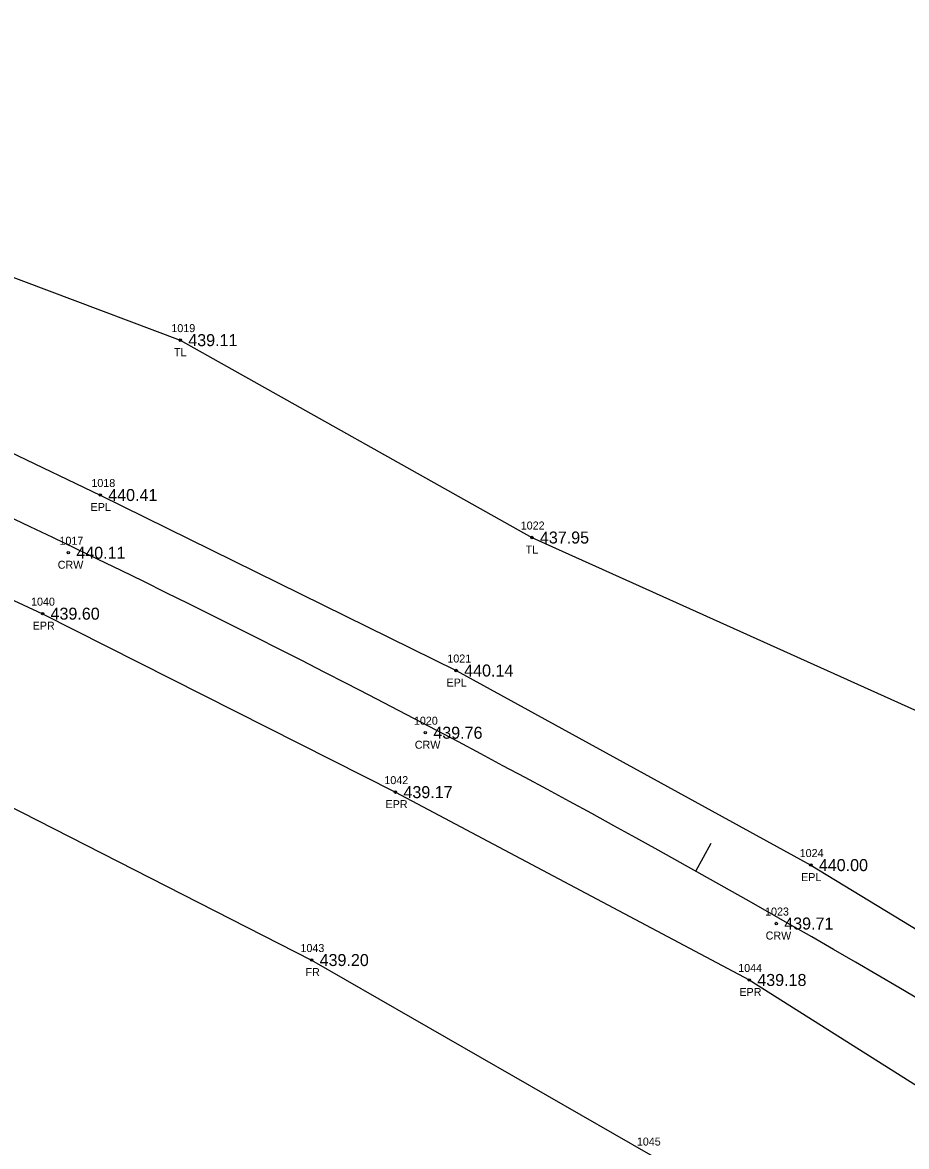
# Model space of a CAD drawing. Extents: x 1611865 to 1617004, y 775289 to 778546.
# Drawn here: x 1613950.5 to 1614060.8, y 777980.8 to 778121.2 of the extents above; entities that cross this region are included whole.
import ezdxf

# ---------------------------------------------------------------- set-up
doc = ezdxf.new("R2010")
doc.units = 0
for name, color, linetype in [('Default', 7, 'Continuous'), ('RD_EX_Fence_Other', 7, 'Continuous'), ('RD_EX_Fence_Other_txCode', 7, 'Continuous'), ('RD_EX_Road', 7, 'Continuous'), ('RD_EX_Road_txCode', 7, 'Continuous'), ('RD_EX_TX_Fence_Other_ELEV', 7, 'Continuous'), ('RD_EX_TX_Road_ELEV', 7, 'Continuous'), ('RD_EX_TX_VEG_ELEV', 7, 'Continuous'), ('RD_EX_VEG', 7, 'Continuous'), ('RD_EX_VEG_txCode', 7, 'Continuous'), ('RD_HC_Cl', 7, 'Continuous'), ('RD_HC_Data_Tic', 7, 'Continuous'), ('RD_HC_Survey_ELEV', 7, 'Continuous'), ('RD_HC_Survey_txCode', 7, 'Continuous'), ('RD_SMD_Locator', 7, 'Continuous')]:
    doc.layers.add(name, color=color, linetype=linetype)

msp = doc.modelspace()

# ---------------------------------------------------------------- linework, layer by layer
at = {"layer": 'Default'}
msp.add_arc((1613334.62, 776765.46), 1432.38, 51.01411, 67.14296, dxfattribs=at)
msp.add_arc((1613334.62, 776765.46), 1432.38, 51.01411, 67.14296, dxfattribs=at)
at = {"layer": 'RD_EX_Fence_Other'}
msp.add_lwpolyline([(1613852.08, 778066.01), (1613898.03, 778046.63), (1613942.24, 778026.73), (1613986.54, 778004.12), (1614028.52, 777979.95), (1614066.85, 777959.39), (1614112.82, 777929.4), (1614150.64, 777902.78), (1614189.71, 777873.35), (1614229.91, 777841.27), (1614268.42, 777810.69), (1614347.33, 777746.8), (1614401.12, 777703.98), (1614396.2, 777691.06)], dxfattribs=at)
at = {"layer": 'RD_EX_Road'}
for points in [[(1613868.87, 778104.15), (1613915.02, 778083.82), (1613960.16, 778062.2), (1614004.58, 778040.28), (1614048.84, 778015.98), (1614091.38, 777990.08), (1614134.36, 777962.6), (1614174.73, 777933.48), (1614192.07, 777920.58), (1614215.93, 777904.23), (1614254.59, 777873.05), (1614293.82, 777842.42), (1614371.74, 777779.59), (1614449.33, 777716.3), (1614443.98, 777709.72), (1614439.38, 777704.09)], [(1613862.14, 778087.92), (1613908.12, 778068.22), (1613952.96, 778047.38), (1613997, 778025.09), (1614041.16, 778001.63), (1614124.35, 777949.06), (1614164.51, 777920.91), (1614187.11, 777904.29), (1614205.27, 777889.82), (1614244.49, 777859.52), (1614283.42, 777829.45), (1614361.06, 777765.89), (1614439.38, 777704.09)]]:
    msp.add_lwpolyline(points, dxfattribs=at)
at = {"layer": 'RD_EX_VEG'}
msp.add_lwpolyline([(1613877.31, 778121.22), (1613921.05, 778100.02), (1613970.15, 778081.54), (1614014.03, 778056.89), (1614062.61, 778034.99), (1614105.06, 778008.15), (1614147.57, 777982.51), (1614187.98, 777952.84), (1614226.4, 777922.61), (1614267.62, 777889.85), (1614307.16, 777859.76), (1614385.12, 777793.65), (1614491.14, 777728.5)], dxfattribs=at)
at = {"layer": 'RD_HC_Cl'}
msp.add_arc((1613334.62, 776765.46), 1432.38, 51.01411, 67.14296, dxfattribs=at)
at = {"layer": 'RD_HC_Data_Tic'}
msp.add_line((1614034.47, 778015.22), (1614036.42, 778018.71), dxfattribs=at)
at = {"layer": 'RD_SMD_Locator'}
for centre in [(1613970.15, 778081.54), (1613960.16, 778062.2), (1614014.03, 778056.89), (1613956.18, 778054.99), (1613952.96, 778047.38), (1614004.58, 778040.28), (1614000.73, 778032.51), (1613997, 778025.09), (1614048.84, 778015.98), (1614044.52, 778008.68), (1613986.54, 778004.12), (1614041.16, 778001.63)]:
    msp.add_circle(centre, 0.15, dxfattribs=at)

# ---------------------------------------------------------------- texts
at = {"layer": 'RD_EX_Fence_Other_txCode'}
for s, p in [('1043', (1613985.15, 778005.12)), ('FR', (1613985.78, 778002.12)), ('1045', (1614027.13, 777980.95))]:
    msp.add_text(s, height=1, dxfattribs=at).set_placement(p)
at = {"layer": 'RD_EX_Road_txCode'}
for s, p in [('1018', (1613959.06, 778063.2)), ('EPL', (1613958.96, 778060.2)), ('1040', (1613951.53, 778048.38)), ('EPR', (1613951.73, 778045.38)), ('1021', (1614003.48, 778041.28)), ('EPL', (1614003.38, 778038.28)), ('1042', (1613995.62, 778026.09)), ('EPR', (1613995.77, 778023.09)), ('1024', (1614047.45, 778016.98)), ('EPL', (1614047.63, 778013.98)), ('1044', (1614039.78, 778002.63)), ('EPR', (1614039.93, 777999.63))]:
    msp.add_text(s, height=1, dxfattribs=at).set_placement(p)
at = {"layer": 'RD_EX_TX_Fence_Other_ELEV'}
msp.add_text('439.20', height=1.5, dxfattribs=at).set_placement((1613987.54, 778003.37))
at = {"layer": 'RD_EX_TX_Road_ELEV'}
for s, p in [('440.41', (1613961.16, 778061.45)), ('439.60', (1613953.96, 778046.63)), ('440.14', (1614005.58, 778039.53)), ('439.17', (1613998, 778024.34)), ('440.00', (1614049.84, 778015.23)), ('439.18', (1614042.16, 778000.88))]:
    msp.add_text(s, height=1.5, dxfattribs=at).set_placement(p)
at = {"layer": 'RD_EX_TX_VEG_ELEV'}
for s, p in [('439.11', (1613971.15, 778080.79)), ('437.95', (1614015.03, 778056.14))]:
    msp.add_text(s, height=1.5, dxfattribs=at).set_placement(p)
at = {"layer": 'RD_EX_VEG_txCode'}
for s, p in [('1019', (1613969.04, 778082.54)), ('TL', (1613969.37, 778079.54)), ('1022', (1614012.64, 778057.89)), ('TL', (1614013.26, 778054.89))]:
    msp.add_text(s, height=1, dxfattribs=at).set_placement(p)
at = {"layer": 'RD_HC_Survey_ELEV'}
for s, p in [('440.11', (1613957.18, 778054.24)), ('439.76', (1614001.73, 778031.76)), ('439.71', (1614045.52, 778007.93))]:
    msp.add_text(s, height=1.5, dxfattribs=at).set_placement(p)
at = {"layer": 'RD_HC_Survey_txCode'}
for s, p in [('1017', (1613955.08, 778055.99)), ('CRW', (1613954.86, 778052.99)), ('1020', (1613999.31, 778033.51)), ('CRW', (1613999.42, 778030.51)), ('1023', (1614043.13, 778009.68)), ('CRW', (1614043.2, 778006.68))]:
    msp.add_text(s, height=1, dxfattribs=at).set_placement(p)

doc.saveas('drawing.dxf')
